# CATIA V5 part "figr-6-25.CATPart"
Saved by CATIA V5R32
Part number: Part1
Bounding box of the stored display mesh (mm): x -120 to 0, y 0 to 90, z -45 to 145
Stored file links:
  D:\PROJECTS\Project 2022\CATIA V5 6R 2022\Resources\Part Files\c06_catia_v5_6r2022_prt\figr-6-25.CATPart
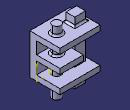
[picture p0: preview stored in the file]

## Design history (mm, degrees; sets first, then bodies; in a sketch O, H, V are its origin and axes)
Body1 (main body)
  Sketch1 on zx-plane, origin (0, 0, 0), H (-1, 0, 0), V (0, 0, 1)
    line L1 (0, 0) -> (120, 0)
    line L2 (120, 0) -> (120, 120)
    line L3 (120, 120) -> (0, 120)
    line L4 (0, 120) -> (0, 0)
    length L3 = 120
    length L2 = 120
    horizontal: L1 H, L3 H
    vertical: L2 V, L4 V
  Pad1: profile Sketch1, direction (0, 1, 0), length 20
  Sketch2 on end face of Pad1, origin (0, 20, 0), H (-1, 0, 0), V (0, 0, 1)
    projected line E1 (120, 120) -> (0, 120) from edge [face of Pad1 from Sketch1.L3 | end face of Pad1]
    point P1 (120, 120)
    line L1 (120, 120) -> (120, 104)
    line L2 (120, 104) -> (0, 104)
    line L3 (0, 104) -> (0, 120)
    point P3 (120, 120)
    length L1 = 16
    horizontal: L2 H
    vertical: L1 V, L3 V
    coincidence: P1 P3
  Sketch3 on end face of Pad1, origin (0, 20, 0), H (-1, 0, 0), V (0, 0, 1)
  Pad2: profile Sketch2, direction (0, 1, 0), length 70
  Sketch4 on end face of Pad1, origin (0, 20, 0), H (-1, 0, 0), V (0, 0, 1)
    projected line E1 (0, 0) -> (120, 0) from edge [face of Pad1 from Sketch1.L1 | end face of Pad1]
    point P1 (0, 0)
    point P3 (0, 16)
    line L1 (0, 16) -> (120, 16)
    line L2 (120, 16) -> (120, 0)
    line L3 (0, 0) -> (0, 16)
    point P5 (0, 0)
    length L2 = 16
    coincidence: P3 V, P1 P5
    horizontal: L1 H
    vertical: L2 V, L3 V
  Pad3: profile Sketch4, direction (0, 1, 0), length 70
  Sketch5 on end face of Pad1, origin (0, 20, 0), H (-1, 0, 0), V (0, 0, 1)
    point P1 (0, 68)
    line L1 (0, 68) -> (70, 68)
    line L2 (70, 68) -> (70, 52)
    line L3 (70, 52) -> (0, 52)
    line L4 (0, 52) -> (0, 68)
    coincidence: P1 V
    horizontal: L1 H, L3 H
    vertical: L2 V, L4 V
  Pad4: profile Sketch5, direction (0, 1, 0), length 70
  Sketch6 on face of Pad2, origin (0, 0, 120), H (1, 0, 0), V (0, 1, 0)
    circle A1 centre (-35, 45) radius 12.5
    radius A1 = 12.5
  Pad5: profile Sketch6, direction (0, 0, 1), length 25, opposite side length 165
  Sketch7 on end face of Pad5, origin (0, 0, 145), H (1, 0, 0), V (0, 1, 0)
    line L1 (-109.2918, 56.9495) -> (-77.2841, 56.9495)
    line L2 (-77.2841, 56.9495) -> (-77.2841, 30.4899)
    line L3 (-77.2841, 30.4899) -> (-109.2918, 30.4899)
    line L4 (-109.2918, 30.4899) -> (-109.2918, 56.9495)
    horizontal: L1 H, L3 H
    vertical: L2 V, L4 V
  Pad6: profile Sketch7, direction (0, 0, 1), length 0, opposite side length 185
  Fillet1: radius 5, on 1 edge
